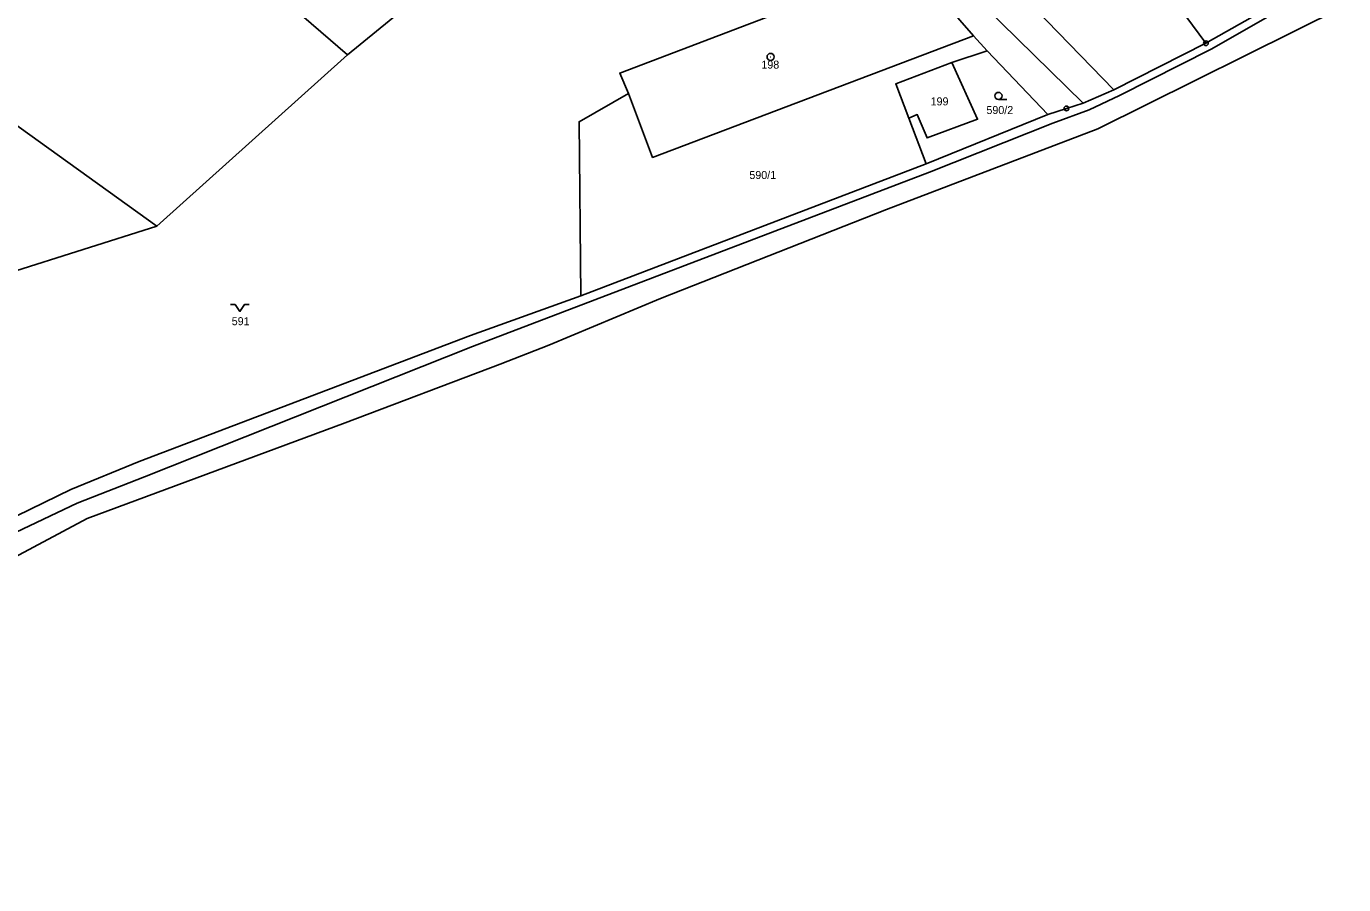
# Model space of a CAD drawing. Extents: x -654083 to -650132, y -1099819 to -1096699.
# Drawn here: x -651096.5 to -650816.7, y -1099749.3 to -1099567.2 of the extents above; entities that cross this region are included whole.
import ezdxf

# ---------------------------------------------------------------- set-up
doc = ezdxf.new("R2010")
doc.units = 0
for name, color, linetype in [('Geodetické body', 7, 'Continuous'), ('Hranice - vnitř_ kresba', 7, 'Continuous'), ('Obvody jako plochy', 7, 'Continuous'), ('Parcelní čísla', 7, 'Continuous'), ('Značky kultur', 7, 'Continuous')]:
    doc.layers.add(name, color=color, linetype=linetype)

msp = doc.modelspace()

# ---------------------------------------------------------------- linework, layer by layer
at = {"layer": 'Geodetické body'}
for centre, radius in [((-650845.98, -1099570.75), 0.5), ((-650845.98, -1099570.75), 0.001), ((-650875.62, -1099584.59), 0.5), ((-650875.62, -1099584.59), 0.001)]:
    msp.add_circle(centre, radius, dxfattribs=at)
at = {"layer": 'Hranice - vnitř_ kresba'}
for p, q in [((-650827.38, -1099561.99), (-650844.85, -1099571.97)), ((-650844.85, -1099571.97), (-650864.36, -1099581.84)), ((-650864.36, -1099581.84), (-650870.76, -1099584.87)), ((-650870.76, -1099584.87), (-650878.5, -1099587.71)), ((-650878.5, -1099587.71), (-650904.72, -1099598.1)), ((-650904.72, -1099598.1), (-651001.75, -1099635.13)), ((-651001.75, -1099635.13), (-651071.38, -1099662.77)), ((-651071.38, -1099662.77), (-651085.68, -1099668.4)), ((-651085.68, -1099668.4), (-651100.15, -1099675.26))]:
    msp.add_line(p, q, dxfattribs=at)
at = {"layer": 'Obvody jako plochy'}
for points in [[(-650965.16, -1099482.13), (-650989.75, -1099459.95), (-651015.14, -1099438.56), (-651043.54, -1099419.8), (-651071.9, -1099398.16), (-651102.24, -1099375.24), (-651111.65, -1099367.47), (-651119.12, -1099374.35), (-651109.32, -1099381.17), (-651012.39, -1099452.17), (-650950.57, -1099506.77), (-650948.73, -1099508.29), (-650872.05, -1099583.45), (-650865.57, -1099580.66), (-650936.39, -1099507.62), (-650941.65, -1099502.66)], [(-650853.98, -1099529.78), (-650850.5, -1099533.39), (-650855.83, -1099537.92), (-650864.8, -1099545.24), (-650845.98, -1099570.75), (-650865.57, -1099580.66), (-650936.39, -1099507.62), (-650898.03, -1099474.25), (-650886.72, -1099488.82), (-650858.82, -1099523.39)], [(-650978.71, -1099624.35), (-650979.09, -1099587.39), (-650968.59, -1099581.42), (-650970.48, -1099577.07), (-650908.84, -1099553.63), (-650895.35, -1099569.16), (-650892.47, -1099572.36), (-650879.55, -1099585.83), (-650875.62, -1099584.59), (-650872.05, -1099583.45), (-650948.73, -1099508.29), (-650950.57, -1099506.77), (-650983.27, -1099536.39), (-651028.28, -1099573.23), (-651068.77, -1099609.57), (-651100.04, -1099619.5), (-651206.51, -1099710.32), (-651224.99, -1099749.34), (-651160.07, -1099704.89), (-651142.25, -1099694.62), (-651101.41, -1099672.46), (-651087.03, -1099665.49), (-651072.53, -1099659.52), (-651002.17, -1099632.78)], [(-651028.28, -1099573.23), (-651064.31, -1099542.1), (-651027.99, -1099505.28), (-650983.27, -1099536.39)], [(-651028.28, -1099573.23), (-651064.31, -1099542.1), (-651104.04, -1099511.72), (-651143.97, -1099555.51), (-651068.77, -1099609.57)], [(-651100.04, -1099619.5), (-651068.77, -1099609.57), (-651143.97, -1099555.51), (-651192.17, -1099520.98), (-651195.54, -1099525.61), (-651196.8, -1099551.52), (-651182.56, -1099563.08), (-651130.53, -1099602.42), (-651101.73, -1099618.35)], [(-650855.5, -1099538.4), (-650852.92, -1099541.45), (-650848.24, -1099547.6), (-650854.89, -1099550.8), (-650849.94, -1099559.73), (-650845.14, -1099557.04), (-650845.32, -1099556.74), (-650841.71, -1099554.64), (-650836.11, -1099565.15), (-650845.98, -1099570.75), (-650864.8, -1099545.24), (-650855.83, -1099537.92)], [(-650970.48, -1099577.07), (-650968.59, -1099581.42), (-650963.5, -1099594.96), (-650895.35, -1099569.16), (-650908.84, -1099553.63)], [(-650899.93, -1099574.83), (-650892.47, -1099572.36), (-650895.35, -1099569.16), (-650963.5, -1099594.96), (-650968.59, -1099581.42), (-650979.09, -1099587.39), (-650978.71, -1099624.35), (-650905.42, -1099596.33), (-650909.1, -1099586.64), (-650911.87, -1099579.35)], [(-650909.1, -1099586.64), (-650907.3, -1099585.89), (-650905.2, -1099590.82), (-650894.49, -1099586.86), (-650899.93, -1099574.83), (-650892.47, -1099572.36), (-650879.55, -1099585.83), (-650905.42, -1099596.33)], [(-650894.49, -1099586.86), (-650899.93, -1099574.83), (-650911.87, -1099579.35), (-650909.1, -1099586.64), (-650907.3, -1099585.89), (-650905.2, -1099590.82)], [(-650907.3, -1099585.89), (-650905.2, -1099590.82), (-650894.49, -1099586.86), (-650899.93, -1099574.83), (-650911.87, -1099579.35), (-650909.1, -1099586.64)]]:
    msp.add_lwpolyline(points, close=True, dxfattribs=at)
for points in [[(-651121.96, -1099692.1), (-651083.58, -1099671.59), (-651028.77, -1099651.3), (-650995.85, -1099638.83), (-650985.53, -1099634.81), (-650961.79, -1099624.89), (-650913.84, -1099606.02), (-650868.91, -1099588.94), (-650816.74, -1099562.99)], [(-650836.11, -1099565.15), (-650845.98, -1099570.75), (-650865.57, -1099580.66), (-650872.05, -1099583.45), (-650875.62, -1099584.59), (-650879.55, -1099585.83), (-650905.42, -1099596.33), (-650978.71, -1099624.35), (-651002.17, -1099632.78), (-651072.53, -1099659.52), (-651087.03, -1099665.49), (-651101.41, -1099672.46)]]:
    msp.add_lwpolyline(points, dxfattribs=at)
for radius in [0.75, 0.001]:
    msp.add_circle((-650938.44, -1099573.64), radius, dxfattribs=at)
at = {"layer": 'Značky kultur'}
msp.add_line((-650888.29, -1099582.67), (-650890.04, -1099582.67), dxfattribs=at)
msp.add_lwpolyline([(-651053.14, -1099626.18), (-651052.14, -1099626.18), (-651051.14, -1099627.68), (-651050.14, -1099626.18), (-651049.14, -1099626.18)], dxfattribs=at)
msp.add_circle((-650890.04, -1099581.92), 0.75, dxfattribs=at)

# ---------------------------------------------------------------- texts
at = {"layer": 'Parcelní čísla'}
for s, p in [('198', (-650940.39, -1099576.13)), ('199', (-650904.45, -1099583.93)), ('590/2', (-650892.6, -1099585.77)), ('590/1', (-650942.94, -1099599.56)), ('591', (-651052.86, -1099630.59))]:
    msp.add_text(s, height=1.7, dxfattribs=at).set_placement(p)

doc.saveas('drawing.dxf')
